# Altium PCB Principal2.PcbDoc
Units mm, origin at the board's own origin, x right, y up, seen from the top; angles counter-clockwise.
Board outline 152.4 x 101.6 mm, 2 copper layers (Top Layer, Bottom Layer); 36 components, 54 nets, 186 pads, 45 vias.
Unrouted connection lines stored in the file: 1.
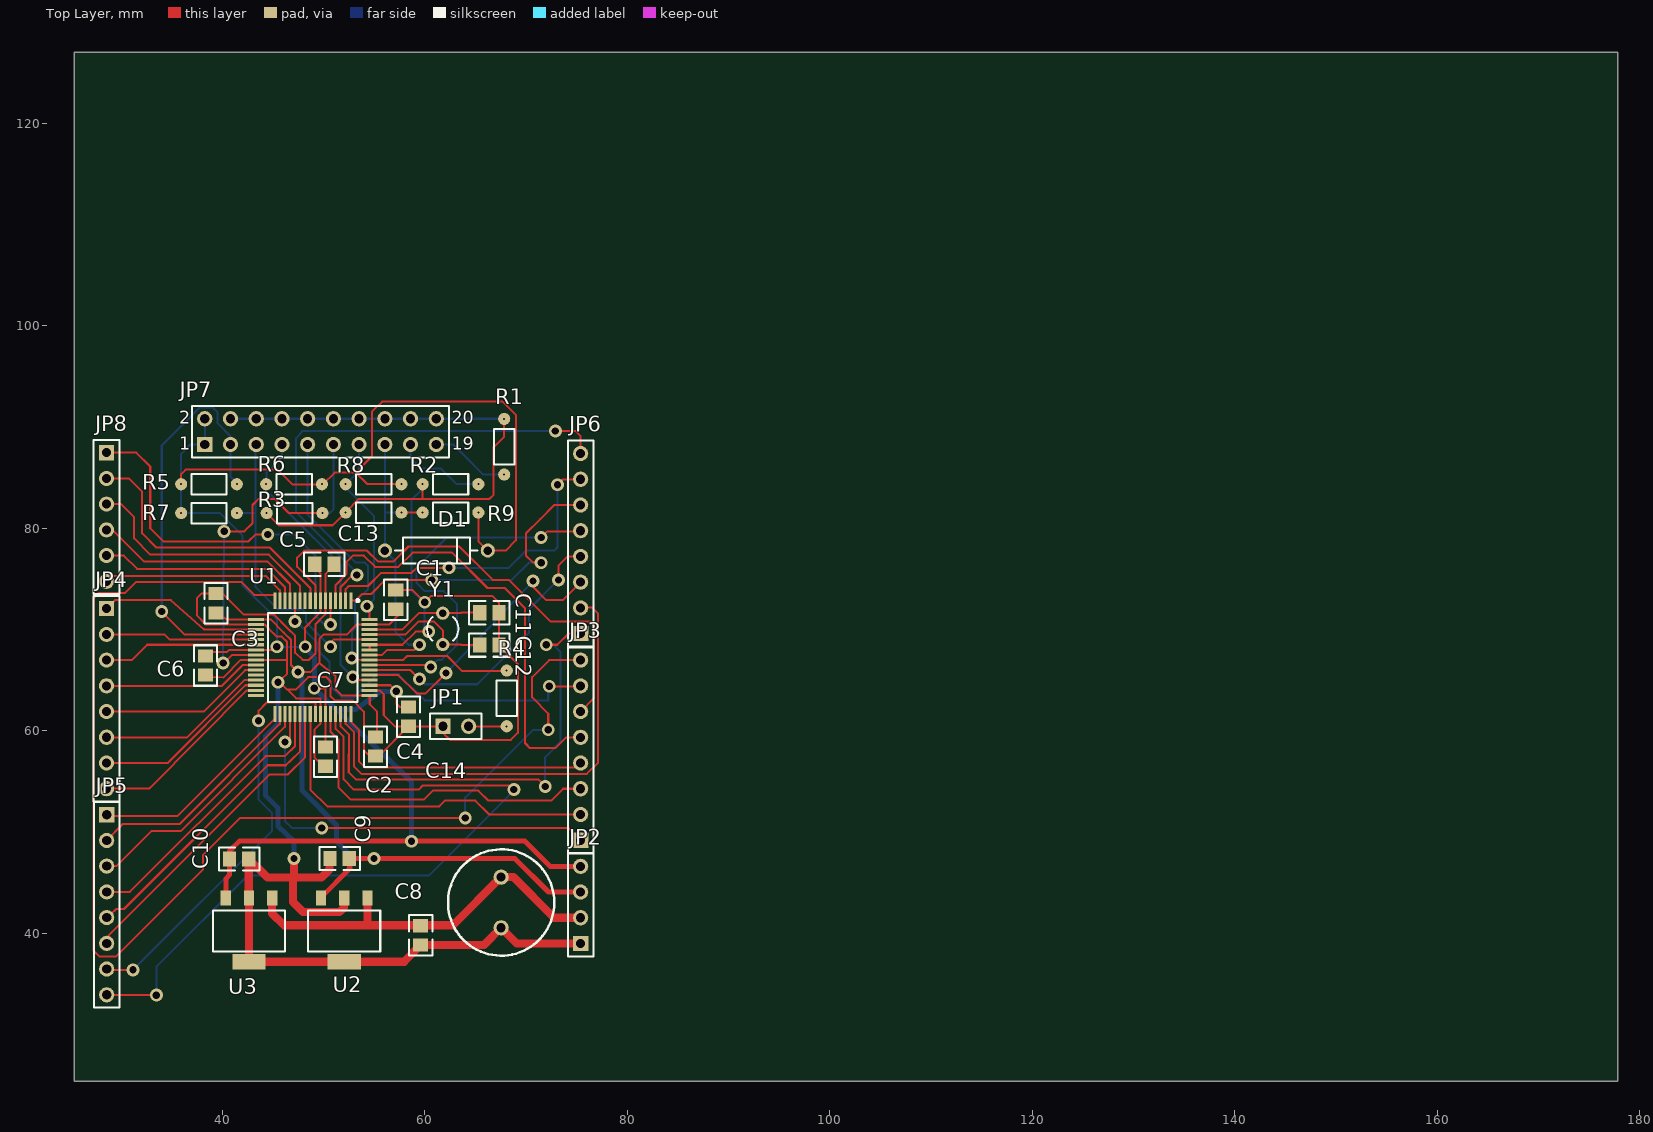
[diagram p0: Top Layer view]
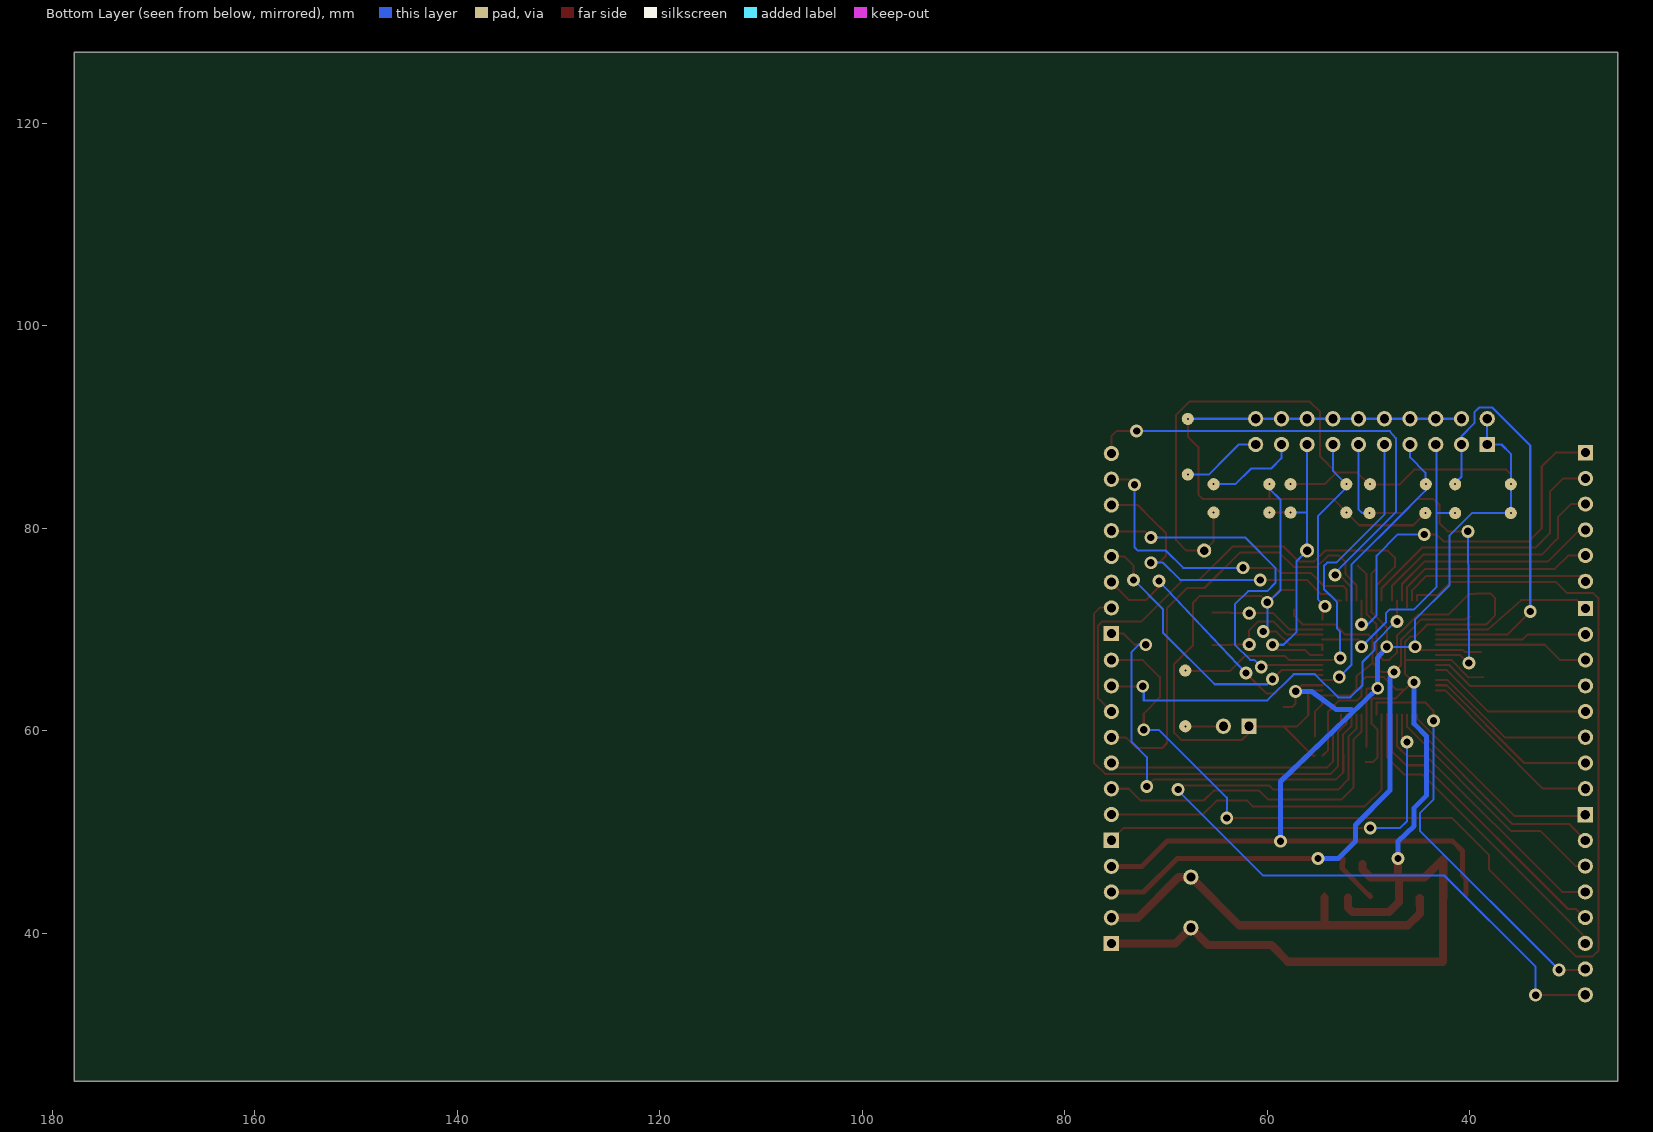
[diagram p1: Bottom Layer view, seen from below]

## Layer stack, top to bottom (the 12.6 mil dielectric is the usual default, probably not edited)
Top Layer: signal copper 0.0356
Dielectric: dielectric 0.32, FR-4, Dk 4.8
Bottom Layer: signal copper 0.0356

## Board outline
25.4,25.4 177.8,25.4 177.8,127 25.4,127

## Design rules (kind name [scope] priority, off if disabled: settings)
Clearance [All] p1: gap=0.2
ComponentClearance [All] p1: gap=0.254 collisioncheckmode=0
PolygonConnect [All] p1: connectstyle=Relief reliefconductorwidth=0.254 reliefentries=4 polygonreliefangle="90 Angle"
RoomDefinition Principal [InComponentClass('Principal')] p1: confinementstyle=ConfineIn formatcopy=TRUE outline 26.6,27.316 140.9,27.316 140.9,115.2 26.6,115.2
RoutingLayers [All] p1: top layer=Horizontal bottom layer=Vertical
RoutingVias [All] p1: holewidth=0.711 width=1.27 viastyle="Through Hole" minholewidth=0.711 minwidth=1.27 maxholewidth=0.711 maxwidth=1.27
SolderMaskExpansion [All] p1: expansion=0.102
TestPointUsage [All] p1: valid=0 allowmultiple=FALSE
Testpoint [All] p1: side=15 testpointundercomponent=TRUE minsize=1.016 maxsize=2.54 preferedsize=1.524 minholesize=0 maxholesize=1.016 preferedholesize=0.813 testpointgrid=0.025 style=1023 order=-539222988
Width [All] p1: maxlimit=0.8 minlimit=0.2 preferedwidth=0.2
16 further rules are at their usual default settings.

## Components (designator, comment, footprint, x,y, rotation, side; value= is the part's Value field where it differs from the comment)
C1 "Cap" R2012-0805 57.15,72.95 r270 top
C2 "Cap" R2012-0805 55.15,58.45 r90 top
C3 "Cap" R2012-0805 39.4,72.6 r270 top
C4 "Cap" R2012-0805 58.4,61.4 r90 top
C5 "Cap" R2012-0805 50.1,76.45 r180 top
C6 "Cap" R2012-0805 38.35,66.45 r90 top
C7 "Cap" R2012-0805 50.2,57.45 r90 top
C8 "Cap" R2012-0805 59.6,39.8 r90 top
C9 "Cap" R2012-0805 51.6,47.4 r0 top
C10 "Cap" R2012-0805 41.676,47.348 r180 top
C11 "Cap" R2012-0805 66.384,71.664 r0 top
C12 "Cap" R2012-0805 66.384,68.464 r0 top
C13 "Cap" "Res 5mm" 57.7,81.55 r180 top
C14 "Cap Pol1" RB5-10.5 67.55,43.05 r270 top
D1 "Diode" DIODE-0.4 61.15,77.8 r0 top
JP1 "JTAG" HDR1X2 61.8,60.45 r0 top
JP2 "Header 4" HDR1X4 75.4,39 r90 top
JP3 "Header 8" HDR1X8 75.4,49.2 r90 top
JP4 "Header 8" HDR1X8 28.584,72.064 r270 top
JP5 "Header 8" HDR1X8 28.6,51.716 r270 top
JP6 "Header 8" HDR1X8 75.4,69.6 r90 top
JP7 "JTAG P5" HDR2X10 38.284,88.276 r0 top
JP8 "Header 6" HDR1X6 28.584,87.464 r270 top
R1 "Res1" "Res 5mm" 67.85,85.3 r90 top
R2 "Res1" "Res 5mm" 65.3,84.35 r180 top
R3 "Res1" "Res 5mm" 49.9,81.5 r180 top
R4 "Res1" "Res 5mm" 68.1,65.95 r270 top
R5 "Res1" "Res 5mm" 35.95,84.35 r0 top
R6 "Res1" "Res 5mm" 49.85,84.35 r180 top
R7 "Res1" "Res 5mm" 35.95,81.5 r0 top
R8 "Res1" "Res 5mm" 57.7,84.35 r180 top
R9 "Res1" "Res 5mm" 59.8,81.55 r0 top
U1 "LPC2114/LPC2124" F-QFP10X10-G64/P.5N 48.95,67.25 r270 top
U2 "LD1117S18" SOT223 58.15,37.2 r180 top
U3 "LD1117S33" SOT223 48.75,37.2 r180 top
Y1 "XTAL 16Mhz" BCY-W2/D3.1 61.784,70.064 r180 top

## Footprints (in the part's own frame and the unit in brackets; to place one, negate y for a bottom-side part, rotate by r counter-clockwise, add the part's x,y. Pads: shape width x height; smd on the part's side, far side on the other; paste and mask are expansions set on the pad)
BCY-W2/D3.1 [mm]
  round 1.3 hole 0.7: 1(0,1.55) 2(0,-1.55)
  silkscreen extent -1.55,-1.19 1.55,1.17
DIODE-0.4 [mm]
  round 1.4 hole 0.85: 1(-5.08,0) 2(5.08,0)
  silkscreen extent -4.06,-1.27 4.06,1.27
F-QFP10X10-G64/P.5N [mm]
  rect 1.6x0.3 smd: 1(-5.6,3.75) 2(-5.6,3.25) 3(-5.6,2.75) 4(-5.6,2.25) 5(-5.6,1.75) 6(-5.6,1.25) 7(-5.6,0.75) 8(-5.6,0.25) 9(-5.6,-0.25) 10(-5.6,-0.75) 11(-5.6,-1.25) 12(-5.6,-1.75) 13(-5.6,-2.25) 14(-5.6,-2.75) 15(-5.6,-3.25) 16(-5.6,-3.75) 33(5.6,-3.75) 34(5.6,-3.25) 35(5.6,-2.75) 36(5.6,-2.25) 37(5.6,-1.75) 38(5.6,-1.25) 39(5.6,-0.75) 40(5.6,-0.25) 41(5.6,0.25) 42(5.6,0.75) 43(5.6,1.25) 44(5.6,1.75) 45(5.6,2.25) 46(5.6,2.75) 47(5.6,3.25) 48(5.6,3.75)
  rect 0.3x1.6 smd: 17(-3.75,-5.6) 18(-3.25,-5.6) 19(-2.75,-5.6) 20(-2.25,-5.6) 21(-1.75,-5.6) 22(-1.25,-5.6) 23(-0.75,-5.6) 24(-0.25,-5.6) 25(0.25,-5.6) 26(0.75,-5.6) 27(1.25,-5.6) 28(1.75,-5.6) 29(2.25,-5.6) 30(2.75,-5.6) 31(3.25,-5.6) 32(3.75,-5.6) 49(3.75,5.6) 50(3.25,5.6) 51(2.75,5.6) 52(2.25,5.6) 53(1.75,5.6) 54(1.25,5.6) 55(0.75,5.6) 56(0.25,5.6) 57(-0.25,5.6) 58(-0.75,5.6) 59(-1.25,5.6) 60(-1.75,5.6) 61(-2.25,5.6) 62(-2.75,5.6) 63(-3.25,5.6) 64(-3.75,5.6)
  silkscreen extent -5.72,-4.4 4.4,4.58
HDR1X2 [mm]
  rect 1.5x1.5 hole 0.9: 1(0,0)
  round 1.5 hole 0.9: 2(2.54,0)
  silkscreen extent -1.27,-1.27 3.81,1.27
HDR1X4 [mm]
  rect 1.5x1.5 hole 0.9: 1(0,0)
  round 1.5 hole 0.9: 2(2.54,0) 3(5.08,0) 4(7.62,0)
  silkscreen extent -1.27,-1.27 8.89,1.27
HDR1X6 [mm]
  rect 1.5x1.5 hole 0.9: 1(0,0)
  round 1.5 hole 0.9: 2(2.54,0) 3(5.08,0) 4(7.62,0) 5(10.16,0) 6(12.7,0)
  silkscreen extent -1.27,-1.27 13.97,1.27
HDR1X8 [mm]
  rect 1.5x1.5 hole 0.9: 1(0,0)
  round 1.5 hole 0.9: 2(2.54,0) 3(5.08,0) 4(7.62,0) 5(10.16,0) 6(12.7,0) 7(15.24,0) 8(17.78,0)
  silkscreen extent -1.27,-1.27 19.05,1.27
HDR2X10 [mm]
  rect 1.5x1.5 hole 0.9: 1(0,0)
  round 1.5 hole 0.9: 2(0,2.54) 3(2.54,0) 4(2.54,2.54) 5(5.08,0) 6(5.08,2.54) 7(7.62,0) 8(7.62,2.54) 9(10.16,0) 10(10.16,2.54) 11(12.7,0) 12(12.7,2.54) 13(15.24,0) 14(15.24,2.54) 15(17.78,0) 16(17.78,2.54) 17(20.32,0) 18(20.32,2.54) 19(22.86,0) 20(22.86,2.54)
  silkscreen extent -1.27,-1.27 24.13,3.81
R2012-0805 [mm]
  rect 1.3x1.5 smd: 1(-0.95,0) 2(0.95,0)
  silkscreen extent -2,-1.15 2,1.15
RB5-10.5 [mm]
  round 1.5 hole 0.9: 1(-2.5,0) 2(2.5,0)
  silkscreen extent -5.25,-5.25 5.25,5.25
"Res 5mm" [mm]
  round 1.2 hole 0.2: 1(0,0) 2(5.5,0)
  silkscreen extent 1,-1.02 4.5,1.02
SOT223 [mm]
  rect 1x1.5 smd: 1(3.8,-6.3) 3(8.4,-6.3) 4(6.1,-6.3)
  rect 3.3x1.5 smd: 4(6.096,0)
  silkscreen extent 2.54,-5.08 9.65,-1.02

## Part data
C1 C2 C3 C4 C5 C6 C7 C8 C9 C10 C11 C12 C13: "Capacitor"
C14: "Polarized Capacitor (Radial)"
D1: "Default Diode"
JP1 JP2: library part "Header 2", "Header, 2-Pin"
JP3 JP4 JP5 JP6: "Header, 8-Pin"
JP7: library part "Header 10X2", "Header, 10-Pin, Dual row"
JP8: "Header, 6-Pin"
R1 R2 R3 R4 R5 R6 R7 R8 R9: "Resistor"
U2 U3: library part LF27ACDT, "Very Low Drop Voltage Regulator with Inhibit"
Y1: library part XTAL, "Crystal Oscillator"

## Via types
v1: diameter 1.27, hole 0.711, Top Layer to Bottom Layer, 45 vias

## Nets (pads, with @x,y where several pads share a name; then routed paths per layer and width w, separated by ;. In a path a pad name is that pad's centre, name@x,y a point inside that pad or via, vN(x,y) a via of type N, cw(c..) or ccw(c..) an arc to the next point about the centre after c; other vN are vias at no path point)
GND: C1.1 C2.1 C3.1 C4.1 C5.1 C6.1 C7.1 C8.1 C9.1 C10.1 C11.2 C12.2 C13.2 C14.2 JP1.1 JP2.1 JP7.4 JP7.6 JP7.8 JP7.10 JP7.12 JP7.14 JP7.16 JP7.18 JP7.20 R1.2 R2.2 R3.2 U1.6 U1.18 U1.25 U1.42 U1.50 U1.58 U1.59 U2.4 U3.4 | length 292.3
  Top Layer w0.2: C6.1@38.7,65.3 40.138,65.282 41.856,67 43.325,67 46.4,67 ; R3.2 45.6,80.3 49.5,80.3 50.9,80.3 52.2,81.6 53.5,82.9 66.4,82.9 66.8,83.3 66.8,88 67.85,89.05 R1.2 ; 46.4,64.1 47.3,64.1 48.5,65.3 50.3,65.3 50.7,64.9 50.7,63.4 51.1,63 52.9,63 54,61.9 54,58.1 C2.1@54.55,57.55 ; 49.4,70.7 49.2,70.5 ; C7.1@50.3,56.9 49.6,56.9 49.1,57.4 49.1,60.1 49.7,60.7 49.7,63.2 47.3,63.2 45.7,64.8 v1(45.5,64.8) 46.4,65.6 46.4,68.8 45.9,69.3 45.4,69.3 45.1,69.6 44.6,70.1 44.2,70.5 38.4,70.5 37.5,71.4 37.5,73.1 37.95,73.55 C3.1 39.45,73.5 40.1,73.5 42.1,71.5 45.1,71.5 46.5,70.1 47.2,69.4 47.2,67.7 47.942,67.005 48.578,67.005 49.2,67.6 49.2,68.8 49.2,69.9 49.2,70.5 ; C5.1@51.05,76.3 50.2,75.45 50.2,71.5 49.2,70.5 ; U1.50@54.575,64 55.562,64 55.956,63.606 55.956,61.544 57.05,60.45 C4.1 ; U1.58@54.575,68 54.575,68.5 57.8,68.5 59.1,69.8 v1@60.1,69.8 ; C2.1@55.35,57.5 55.3,57.55 55.5,57.55 C4.1 ; C1.1@57.35,73.9 58.8,73.9 v1(60,72.7) 60.6,73.3 66.7,73.3 67.334,72.666 C11.2 C12.2 69.2,66.6 69.2,59.8 68.5,59.1 62.5,59.1 61.8,59.8 JP1.1 C4.1 ; 59.8,82.9 R2.2 ; JP7.20 JP7.20@61.144,90.83
  Top Layer w0.8: 47,45.5 47,43.1 48,42.1 51.6,42.1 52.05,42.55 U2.4@52.05,43.55 ; 47.1,45.5 v1(47.1,47.4) ; C9.1@50.6,46.847 50.6,46.3 49.8,45.5 44.474,45.5 C10.1 42.626,43.524 42.654,43.496 42.654,37.2 52.054,37.2 58,37.2 58,37.25 C8.1 65.85,38.85 C14.2 69.084,39.016 JP2.1@75.3,39.016
  Bottom Layer w0.2: JP7.4 67.834,90.816 R1.2 ; R2.2 59.8,83.9 58.7,82.8 58.7,73.9 59.9,72.7 v1(60,72.7) 60,70.2 v1(60.4,69.8)
  Bottom Layer w0.5: v1(45.5,64.8) 45.5,60.7 44.3,59.5 44.3,53.6 45.5,52.4 45.5,50.6 47.1,49.1 v1(47.1,47.4)
NetC1_2: C1.2 C2.2 C3.2 C9.2 JP2.3 U1.17 U1.49 U1.63 U2.3 | length 89.4
  Top Layer w0.2: C3.2@40,71.3 40.477,71 43.325,71 U1.17 44.8,71 46.1,69.7 46.8,69 46.8,66.5 v1(47.5,65.8) ; v1@47.7,66.3 v1(47.5,65.8) ; U2.3@49.834,43.628 U2.3@49.834,43.917 ; C2.2@55.3,59.45 55.3,61.9 54.575,62.625 54.575,63.5 51.8,63.5 51.2,64.1 51.2,65.4 49.6,66.7 ; C1.2@57.35,72 57.35,71.35 56.5,70.5 53.299,70.5 52.967,70.168 52.967,70.171 52.3,69.5 50,69.5 49.6,69.1 49.6,66.7 ; v1(47.5,65.8) 48.7,65.8 49.6,66.7
  Top Layer w0.5: U2.3@49.834,43.628 52.6,46.4 C9.2 68.9,47.4 72.22,44.08 JP2.3
  Bottom Layer w0.5: v1(47.5,65.8) 47.9,65.282 47.9,54.1 51.3,50.7 51.3,49.1 53,47.4 v1(55,47.4)
NetC4_2: C4.2 C5.2 C6.2 C7.2 C10.2 D1.2 JP2.4 JP7.1 JP7.2 R5.1 R6.1 R7.1 R8.1 R9.2 U1.7 U1.23 U1.43 U1.51 U3.3 | length 197.2
  Top Layer w0.2: R5.1 35.95,85.35 36.4,85.8 45.5,85.8 46.991,84.309 R6.1@49.874,84.309 ; C6.2@38.9,67.8 40.5,67.8 40.708,68 45.2,68 v1(45.4,68.3) ; v1@48.158,68.25 v1(48.2,68.3) 48.2,70.2 49.2,71.2 49.7,71.7 49.7,75.55 C5.2@49.15,76.1 ; v1(49.1,64.2) 50.2,64.2 50.2,59 C7.2 ; R6.1 49.95,84.35 51.1,85.5 53.2,85.5 ; U1.51@54.575,64.5 56.6,64.5 v1(57.2,63.9) 57.2,62.7 57.55,62.35 C4.2 ; R8.1 54.35,84.35 53.2,85.5 ; R9.2 65.3,78.73 D1.2 68,77.8 69,78.8 69,91.2 67.7,92.5 55.8,92.5 54.788,91.488 54.788,87.088 53.2,85.5
  Top Layer w0.5: U3.3@40.4,43.8 40.4,45.4 40.726,45.775 40.726,48.126 41.7,49.1 v1(58.7,49.1) 69.9,49.1 72.38,46.62 JP2.4
  Bottom Layer w0.2: JP7.2 JP7.1 36.876,88.276 35.95,87.35 R7.1 39.8,81.5 42,79.3 42,74.4 45.4,71 v1(45.4,68.3) v1@48.108,68.3
  Bottom Layer w0.5: v1(48.2,68.3) 49.1,67.2 v1(49.1,64.2) 58.7,55 v1(58.7,49.1) ; 51.7,62.1 53.2,62.1 55.659,63.904 v1@57.1,63.9
NetC8_2: C8.2 C14.1 JP2.2 U2.1 U3.1 | length 39.3
  Top Layer w0.2: U2.1@54.334,44.009 54.334,43.79 U2.1@54.553,43.79
  Top Layer w0.8: U3.1 44.934,41.966 46.1,40.8 62.8,40.8 C14.1 68.75,45.55 72.76,41.54 JP2.2 ; 54.3,40.8 54.35,40.85 U2.1@54.35,43.55
NetC11_1: C11.1 U1.62 Y1.2 | length 11.5
  Top Layer w0.2: U1.62@54.575,70 57.8,70 59.414,71.614 63.576,71.614 63.626,71.664 C11.1
NetC12_1: C12.1 U1.61 Y1.1 | length 13.2
  Top Layer w0.2: U1.61@54.575,69.5 58.1,69.5 59.4,70.8 60.9,70.8 61.784,69.916 Y1.1 63.576,68.514 63.626,68.464 C12.1
NetC13_1: C13.1 D1.1 JP7.15 R9.1 U1.57 | length 31.1
  Top Layer w0.2: U1.57@54.575,67.5 55.8,67.5 56.3,68 59,68 v1(59.5,68.5) v1@59.5,68.3 ; C13.1 R9.1
  Bottom Layer w0.2: JP7.15 56.064,77.806 57.1,76.77 57.1,69.8 58.4,68.5 v1(59.5,68.5) ; 56.114,81.55 C13.1
NetJP1_2: JP1.2 R4.2 | length 3.8
  Top Layer w0.2: JP1.2 R4.2
NetJP3_1: JP3.1 U1.36 | length 40.8
  Top Layer w0.2: v1(46.2,58.9) 46.7,59.3 U1.36@46.7,61.625 ; v1(49.835,50.394) 74.206,50.394 JP3.1
  Bottom Layer w0.2: v1(46.2,58.9) 46.2,51.1 46.906,50.394 v1(49.835,50.394)
NetJP3_2: JP3.2 U1.40 | length 35.6
  Top Layer w0.2: U1.40@48.7,61.625 48.7,60.409 48.7,54.2 50.381,52.54 61.44,52.54 62,53.1 65,53.1 66.36,51.74 JP3.2
NetJP3_3: JP3.3 U1.44 | length 33.2
  Top Layer w0.2: U1.44@50.7,61.625 50.7,59.9 51.5,59.1 51.5,54.4 52.7,53.2 59.9,53.2 60.8,54.1 65.3,54.1 66.3,53.1 72.5,53.1 73.68,54.28 JP3.3
NetJP3_4: JP3.4 U1.48 | length 27.2
  Top Layer w0.2: U1.48@52.7,61.625 52.7,60.9 53.5,60.1 53.5,57 54.1,56.4 74.8,56.4 JP3.4
NetJP3_5: JP3.5 U1.4 | length 44.9
  Top Layer w0.2: U1.4@51.2,72.875 51.2,74.4 52.3,75.5 52.3,76.7 52.9,77.3 54,77.3 55.1,76.2 57.4,76.2 58.8,77.6 62.7,77.6 66.2,74.1 67.9,74.1 69.9,72.1 69.9,58.8 70.4,58.3 72.9,58.3 73.96,59.36 JP3.5
NetJP3_6: JP3.6 U1.8 | length 47.9
  Top Layer w0.2: U1.8@49.2,72.875 49.2,74.4 47.4,76.2 47.4,77.1 48.1,77.8 54.3,77.8 55.4,76.7 56.9,76.7 58.4,78.2 63.4,78.2 66.7,74.9 68.3,74.9 72.4,70.8 76.3,70.8 76.7,70.4 76.7,63.2 JP3.6
NetJP3_7: JP3.7 U1.12 | length 39.2
  Top Layer w0.2: v1(47.2,70.8) 47.2,71.958 U1.12@47.2,72.875 ; v1(72.3,64.4) 75.36,64.4 JP3.7
  Bottom Layer w0.2: v1(47.2,70.8) 47.3,70.8 49.4,68.7 49.4,68 50.6,66.8 50.6,64.5 51.8,63.3 53,63.3 55.3,65.6 57.4,65.6 60,63 72.2,63 72.2,64.3 v1(72.3,64.4) ; JP3.7 JP3.7@76.048,64.44
NetJP3_8: JP3.8 U1.16 | length 122.6
  Top Layer w0.2: U1.16@45.2,72.875 45.2,73.431 43.169,73.431 41.9,74.7 31.5,74.7 30.4,73.6 27.8,73.6 27.3,73.1 27.3,38.3 27.9,37.7 29.5,37.7 38.1,46.3 38.1,47.7 41.8,51.4 v1(64,51.4) v1@64.135,51.714 ; v1(72.2,60.1) 72.2,61.7 70.6,63.3 70.6,65.3 72.28,66.98 JP3.8
  Bottom Layer w0.2: v1(64,51.4) 64,53.4 70.7,60.1 v1(72.2,60.1)
NetJP4_1: JP4.1 U1.19 | length 16.2
  Top Layer w0.2: JP4.1 29.418,72.898 34.947,72.898 38.198,70.047 38.245,70 U1.19@43.325,70
NetJP4_2: JP4.2 U1.21 | length 15
  Top Layer w0.2: JP4.2 34.286,69.524 34.81,69 U1.21@43.325,69
NetJP4_3: JP4.3 U1.22 | length 15.4
  Top Layer w0.2: JP4.3 31.084,66.984 32.6,68.5 U1.22@43.325,68.5
NetJP4_4: JP4.4 U1.26 | length 15.6
  Top Layer w0.2: JP4.4 39.981,64.444 42.037,66.5 U1.26@43.325,66.5
NetJP4_5: JP4.5 U1.27 | length 16.4
  Top Layer w0.2: JP4.5 38.18,61.904 42.276,66 U1.27@43.325,66
NetJP4_6: JP4.6 U1.29 | length 17.1
  Top Layer w0.2: JP4.6 36.55,59.364 42.186,65 U1.29@43.325,65
NetJP4_7: JP4.7 U1.30 | length 17.9
  Top Layer w0.2: JP4.7 34.624,56.824 42.3,64.5 U1.30@43.325,64.5
NetJP4_8: JP4.8 U1.31 | length 18.8
  Top Layer w0.2: JP4.8 32.784,54.284 32.9,54.4 ; 32.879,54.4 42.432,64 ; 42.453,64 U1.31@43.325,64
NetJP5_1: JP5.1 U1.33 | length 21
  Top Layer w0.2: JP5.1@28.6,51.6 35.6,51.6 45.2,61.2 U1.33@45.2,61.625
NetJP5_2: JP5.2 U1.34 | length 22.8
  Top Layer w0.2: JP5.2 30.2,50.8 35.8,50.8 45.7,60.7 U1.34@45.7,61.625
NetJP5_3: JP5.3 U1.35 | length 24.5
  Top Layer w0.2: JP5.3 29.542,46.636 33,50.1 35.9,50.1 46.2,60.4 U1.35@46.2,61.625
NetJP5_4: JP5.4 U1.37 | length 27.7
  Top Layer w0.2: JP5.4 30.896,44.096 44.3,57.5 46.2,57.5 47.2,58.5 47.2,60.7 U1.37@47.2,61.625
NetJP5_5: JP5.5 U1.38 | length 29.5
  Top Layer w0.2: JP5.5 29.55,42.406 30.306,42.406 44.5,56.6 46.3,56.6 46.8,57.1 47.7,58 47.7,60.809 U1.38@47.7,61.625
NetJP5_6: JP5.6 U1.39 | length 31.8
  Top Layer w0.2: JP5.6@28.6,39.014 JP5.6 28.8,39.216 28.8,39.8 44.7,55.7 46.5,55.7 48.2,57.4 U1.39
NetJP5_7: JP5.7 U1.41 | length 41.7
  Top Layer w0.2: JP5.7 28.676,36.4 v1(31.2,36.4) ; v1(43.6,61) 43.6,62 44.4,62.8 49.2,62.8 49.2,62.535 U1.41@49.2,61.625
  Bottom Layer w0.2: v1@31.1,36.4 v1(31.2,36.4) 44.9,50.1 44.9,51.9 43.6,53.2 v1(43.6,61)
NetJP5_8: JP5.8 U1.45 | length 74.6
  Top Layer w0.2: JP5.8 28.636,33.9 v1(33.5,33.9) ; U1.45@51.2,61.625 51.2,60.2 52,59.4 52,55.2 53,54.2 59.4,54.2 59.8,54.6 68.3,54.6 v1(68.8,54.2)
  Bottom Layer w0.2: v1(33.5,33.9) 33.5,36.7 42.5,45.7 60.4,45.7 68.7,54 v1(68.8,54.2)
NetJP6_1: JP6.1 U1.46 | length 45.5
  Top Layer w0.2: U1.46@51.7,61.625 51.7,60.449 52.503,59.646 52.5,55.9 53.2,55.2 71.2,55.2 v1(71.9,54.5) ; v1(72,68.5) 73.1,68.5 74.2,69.6 JP6.1
  Bottom Layer w0.2: v1(71.9,54.5) 71.9,57.4 73.4,58.9 73.4,67.8 72.7,68.5 v1(72,68.5)
NetJP6_2: JP6.2 U1.47 | length 47
  Top Layer w0.2: U1.47@52.2,61.625 52.2,60.7 53,59.9 53,56.5 53.747,55.753 76.022,55.753 77.1,56.8 77.1,71.6 76.556,72.161 75.4,72.161 JP6.2
NetJP6_3: JP6.3 U1.53 | length 28.2
  Top Layer w0.2: U1.53@54.575,65.5 57.4,65.5 59.2,63.7 60.1,63.7 v1(62.1,65.7) ; v1(70.7,74.8) 70.7,74.2 72,72.9 73.62,72.9 JP6.3
  Bottom Layer w0.2: v1(62.1,65.7) v1(70.7,74.8)
NetJP6_4: JP6.4 U1.54 | length 29.2
  Top Layer w0.2: U1.54@54.575,66 58.6,66 v1(59.5,65.1) ; v1(73.2,74.9) 73.2,76.3 74.12,77.22 JP6.4
  Bottom Layer w0.2: v1(59.5,65.1) 60,64.6 65.2,64.6 70.3,69.7 70.3,72 v1(73.2,74.9) v1@73.2,74.5
NetJP6_5: JP6.5 U1.55 | length 37.5
  Top Layer w0.2: U1.55@54.575,66.5 v1@60.5,66.5 ; v1(71.5,79.1) 72.1,79.7 75.1,79.7 JP6.5
  Bottom Layer w0.2: v1(60.6,66.3) 61.3,67 61.7,67 63.2,68.5 63.2,72.5 61.9,73.8 60,73.8 59.2,74.6 59.2,76.1 62.2,79.1 v1(71.5,79.1)
NetJP6_6: JP6.6 U1.1 | length 30.9
  Top Layer w0.2: U1.1@52.7,72.875 53.175,72.875 53.8,73.5 54.7,73.5 56.1,74.9 v1(60.7,74.9) ; v1(71.5,76.6) 70.7,76.6 70,77.3 70,79.5 71.4,80.9 72.8,82.3 JP6.6
  Bottom Layer w0.2: v1(60.7,74.9) 68.6,74.9 70.3,76.6 v1(71.5,76.6)
NetJP6_7: JP6.7 U1.2 | length 32.4
  Top Layer w0.2: U1.2@52.2,72.875 52.2,74 52.5,74.3 54.4,74.3 55.7,75.6 58.7,75.6 59.2,76.1 v1(62.4,76.1) ; v1(73.1,84.3) 73.6,84.8 JP6.7
  Bottom Layer w0.2: v1(62.4,76.1) 68.3,76.1 70,77.8 72.8,77.8 73.1,78.1 v1(73.1,84.3)
NetJP6_8: JP6.8 U1.3 | length 49.7
  Top Layer w0.2: U1.3@51.7,72.875 51.7,74.2 52.9,75.4 v1(53.3,75.4) ; v1(72.9,89.6) 74.9,89.6 75.4,89.1 JP6.8
  Bottom Layer w0.2: v1@53.4,75.5 47.3,81.6 47.3,88.9 47.9,89.6 v1(72.9,89.6)
NetJP7_3: JP7.3 R5.2 U1.20 | length 42
  Top Layer w0.2: v1@34.036,71.552 v1(34.036,71.78) ; v1@34.036,71.764 36.3,69.5 U1.20@43.325,69.5
  Bottom Layer w0.2: v1(34.036,71.78) 34.036,88.176 37.782,91.923 39.065,91.923 39.548,91.44 39.548,90.379 40.824,89.103 40.824,85.076 41.45,84.45 R5.2
NetJP7_5: JP7.5 R7.2 U1.60 | length 30.8
  Top Layer w0.2: v1(50.7,68.3) 50.7,68.8 51,69 U1.60 U1.60@54.575,69
  Bottom Layer w0.2: R7.2 42.3,81.5 43.283,81.5 ; JP7.5@43.383,88.276 JP7.5 43.283,88.195 43.283,74.217 45.5,72 47.9,72 48.3,71.6 48.3,70.7 48.8,70.2 v1(50.7,68.3)
NetJP7_7: JP7.7 R6.2 U1.52 | length 29.3
  Top Layer w0.2: v1@52.9,65 v1(52.9,65.3) 53.2,65 U1.52 U1.52@54.575,65
  Bottom Layer w0.2: JP7.7@45.9,88.38 JP7.7 45.904,87.004 44.4,85.5 44.4,83.7 45.4,82.7 46.5,81.6 51.7,76.4 51.7,66.5 v1(52.9,65.3)
NetJP7_9: JP7.9 R4.1 U1.56 | length 40.9
  Top Layer w0.2: v1(52.8,67.2) 53.645,67 54.575,67 57.9,67 58.3,67.4 62.2,67.4 63.7,65.9 68.05,65.9 R4.1
  Bottom Layer w0.2: JP7.9 48.444,81.356 53.2,76.6 54.1,76.6 54.4,76.3 54.4,74 53.1,72.7 53.1,70.1 52.8,69.8 v1(52.8,67.2)
NetJP7_11: JP7.11 R3.1 U1.24 | length 36.8
  Top Layer w0.2: v1(40.1,66.7) 40.2,66.7 41,67.5 41.9,67.5 42.596,67.5 U1.24@43.325,67.5 ; v1(40.2,79.7) 42.2,79.7 43,80.5 43,82.3 43.6,82.9 45.2,82.9 46.6,81.5 R3.1
  Bottom Layer w0.2: v1(40.1,66.7) v1(40.2,79.7) ; R3.1 50.6,81.5 51,81.9 JP7.11@51,88.26
NetJP7_13: JP7.13 R8.2 U1.64 | length 20
  Top Layer w0.2: v1(54.3,72.3) 54.534,72.517 54.534,71 U1.64@54.575,71
  Bottom Layer w0.2: JP7.13@53.416,88.276 JP7.13 53.524,85.674 R8.2 52.2,84 55,81.2 55,73 v1(54.3,72.3)
NetJP7_17: JP7.17 R2.1 | length 9.1
  Bottom Layer w0.2: JP7.17 58.604,86.896 59.6,85.9 61.6,85.9 63.15,84.35 R2.1
NetJP7_19: JP7.19 R1.1 | length 7.9
  Bottom Layer w0.2: JP7.19 62.824,88.276 63.961,87.139 65.8,85.3 R1.1
NetJP8_1: JP8.1 U1.5 | length 39.1
  Top Layer w0.2: JP8.1 31.536,87.464 32.9,86.1 32.9,80 34.2,78.7 42.6,78.7 43.3,79.4 v1(44.5,79.4) ; v1(50.7,70.5) U1.5 U1.5@50.7,72.875
  Bottom Layer w0.2: v1(44.5,79.4) 47.1,79.4 49.2,77.3 49.2,71.4 50.1,70.5 v1(50.7,70.5)
NetJP8_2: JP8.2 U1.9 | length 28.2
  Top Layer w0.2: JP8.2 30.776,84.924 32.1,83.6 32.1,79.5 33.5,78.1 44.7,78.1 48.7,74.1 U1.9@48.7,72.875
NetJP8_3: JP8.3 U1.11 | length 25.1
  Top Layer w0.2: JP8.3 30.016,82.384 31.3,81.1 31.3,79 32.9,77.4 44.6,77.4 47.7,74.3 U1.11@47.7,72.875
NetJP8_4: JP8.4 U1.13 | length 22.1
  Top Layer w0.2: JP8.4 29.156,79.844 29.9,79.1 32.3,76.7 ; 32.2,76.8 32.3,76.7 ; U1.13@46.7,72.875 46.7,74.5 44.5,76.7 32.3,76.7
NetJP8_5: JP8.5 U1.14 | length 20.9
  Top Layer w0.2: JP8.5 30.296,77.304 31.6,76 44.4,76 46.2,74.2 U1.14@46.2,72.187
NetJP8_6: JP8.6 U1.15 | length 19
  Top Layer w0.2: JP8.6 28.584,74.784 29.1,75.3 44.3,75.3 45.7,73.9 U1.15 U1.15@45.7,72.875
pads on no net: U1.10 U1.28 U1.32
